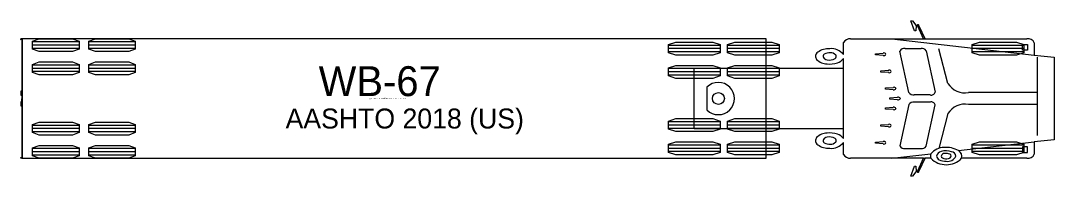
# Model space of a CAD drawing. Extents: x -69 to 14108008, y -6 to 8640172.
# Drawn here: x -69.5 to 4, y -5.5 to 5.5 of the extents above; entities that cross this region are included whole.
import ezdxf

# ---------------------------------------------------------------- set-up
doc = ezdxf.new("R2010")
doc.units = 0
doc.layers.add('AutoTurn4', color=7, linetype='Continuous')

msp = doc.modelspace()

# ---------------------------------------------------------------- linework, layer by layer
at = {"layer": 'AutoTurn4'}
for p, q in [((-5.834, 5.187), (-5.851, 5.209)), ((-5.835, 5.159), (-5.834, 5.187)), ((-69.359, -4.25), (-69.359, 4.25)), ((-65.35, 4.021), (-68.65, 4.021)), ((-65.35, 3.792), (-68.65, 3.792)), ((-61.35, 4.021), (-64.65, 4.021)), ((-61.35, 3.792), (-64.65, 3.792)), ((-19.767, 3.771), (-23.433, 3.771)), ((-15.567, 3.771), (-19.233, 3.771)), ((-11, 3.134), (-11, 3.979)), ((-7.561, 4.25), (2.573, 3.09)), ((-5.311, 4.25), (-5.211, 4.25)), ((1.833, 3.771), (-1.833, 3.771)), ((1.738, 3.841), (2.094, 3.841)), ((1.738, 3.428), (1.738, 3.841)), ((2.094, 3.841), (2.094, 3.428)), ((-65.35, 3.563), (-68.65, 3.563)), ((-61.35, 3.563), (-64.65, 3.563)), ((-19.767, 3.542), (-23.433, 3.542)), ((-19.767, 3.312), (-23.433, 3.312)), ((-15.567, 3.542), (-19.233, 3.542)), ((-15.567, 3.312), (-19.233, 3.312)), ((-8.727, 3.186), (-8.177, 3.225)), ((-8.727, 3.096), (-8.727, 3.186)), ((-8.177, 3.057), (-8.727, 3.096)), ((-6.336, 0.424), (-6.98, 3.36)), ((-6.61, 3.558), (-5.479, 3.558)), ((-5.109, 3.393), (-4.464, 0.457)), ((-3.572, 1.07), (-4.205, 3.537)), ((1.833, 3.542), (-1.833, 3.542)), ((1.833, 3.312), (-1.833, 3.312)), ((2.094, 3.428), (1.738, 3.428)), ((-65.35, 2.371), (-68.65, 2.371)), ((-61.35, 2.371), (-64.65, 2.371)), ((2.799, -2.637), (2.799, 2.926)), ((-65.35, 2.142), (-68.65, 2.142)), ((-65.35, 1.913), (-68.65, 1.913)), ((-61.35, 2.142), (-64.65, 2.142)), ((-61.35, 1.913), (-64.65, 1.913)), ((-19.767, 2.121), (-23.433, 2.121)), ((-19.767, 1.892), (-23.433, 1.892)), ((-19.767, 1.662), (-23.433, 1.662)), ((-15.567, 2.121), (-19.233, 2.121)), ((-15.567, 1.892), (-19.233, 1.892)), ((-15.567, 1.662), (-19.233, 1.662)), ((-11, -2.165), (-11, 2.165)), ((-8.341, 1.969), (-7.766, 2.009)), ((-8.341, 1.879), (-8.341, 1.969)), ((-7.766, 1.841), (-8.341, 1.879)), ((-20.698, 0.803), (-20.698, -0.813)), ((-8.007, 0.751), (-7.457, 0.791)), ((-8.007, 0.661), (-8.007, 0.751)), ((-69.429, 0.259), (-69.43, -0.262)), ((-69.429, 0.266), (-69.429, 0.531)), ((-69.429, 0), (-69.359, 0)), ((-7.457, 0.622), (-8.007, 0.661)), ((-7.698, 0.045), (-7.149, 0.084)), ((-7.698, -0.045), (-7.698, 0.045)), ((-4.835, 0.259), (-5.965, 0.259)), ((2.799, 0.417), (-2.093, 0.417)), ((-69.429, -0.531), (-69.429, -0.266)), ((-8.007, -0.661), (-7.457, -0.622)), ((-8.007, -0.751), (-8.007, -0.661)), ((-7.149, -0.084), (-7.698, -0.045)), ((-6.336, -0.424), (-6.98, -3.36)), ((-4.835, -0.259), (-5.965, -0.259)), ((-5.109, -3.393), (-4.464, -0.457)), ((2.799, -0.417), (-2.093, -0.417)), ((-7.457, -0.791), (-8.007, -0.751)), ((-3.572, -1.07), (-4.208, -3.55)), ((-65.35, -1.912), (-68.65, -1.912)), ((-65.35, -2.142), (-68.65, -2.142)), ((-61.35, -1.912), (-64.65, -1.912)), ((-61.35, -2.142), (-64.65, -2.142)), ((-19.767, -1.662), (-23.433, -1.662)), ((-19.767, -1.892), (-23.433, -1.892)), ((-19.767, -2.121), (-23.433, -2.121)), ((-15.567, -1.662), (-19.233, -1.662)), ((-15.567, -1.892), (-19.233, -1.892)), ((-15.567, -2.121), (-19.233, -2.121)), ((-8.341, -1.879), (-7.791, -1.84)), ((-8.341, -1.969), (-8.341, -1.879)), ((-7.791, -2.008), (-8.341, -1.969)), ((-65.35, -2.371), (-68.65, -2.371)), ((-61.35, -2.371), (-64.65, -2.371)), ((-65.35, -3.562), (-68.65, -3.562)), ((-61.35, -3.562), (-64.65, -3.562)), ((-19.767, -3.312), (-23.433, -3.312)), ((-19.767, -3.542), (-23.433, -3.542)), ((-15.567, -3.312), (-19.233, -3.312)), ((-15.567, -3.542), (-19.233, -3.542)), ((-11, -3.979), (-11, -3.134)), ((-8.727, -3.096), (-8.177, -3.057)), ((-8.727, -3.186), (-8.727, -3.096)), ((-8.177, -3.225), (-8.727, -3.186)), ((-6.61, -3.558), (-5.479, -3.558)), ((-2.818, -3.707), (2.573, -3.09)), ((1.833, -3.312), (-1.833, -3.312)), ((1.833, -3.542), (-1.833, -3.542)), ((2.094, -3.428), (1.738, -3.428)), ((1.738, -3.428), (1.738, -3.841)), ((2.094, -3.841), (2.094, -3.428)), ((-65.35, -3.792), (-68.65, -3.792)), ((-65.35, -4.021), (-68.65, -4.021)), ((-61.35, -3.792), (-64.65, -3.792)), ((-61.35, -4.021), (-64.65, -4.021)), ((-19.767, -3.771), (-23.433, -3.771)), ((-15.567, -3.771), (-19.233, -3.771)), ((-7.561, -4.25), (-4.773, -3.931)), ((-5.311, -4.25), (-5.211, -4.25)), ((2.053, -4.25), (-2.591, -4.25)), ((1.833, -3.771), (-1.833, -3.771)), ((1.738, -3.841), (2.094, -3.841)), ((-5.834, -5.187), (-5.851, -5.209)), ((-5.835, -5.159), (-5.834, -5.187))]:
    msp.add_line(p, q, dxfattribs=at)
for points in [[(-10.487, 4.25), (-5.311, 4.25), (-5.716, 5.146), (-5.717, 5.146), (-5.753, 5.158), (-5.754, 5.158), (-5.755, 5.158), (-5.835, 5.159), (-5.835, 5.158), (-5.851, 4.81), (-5.954, 4.81), (-6.211, 5.529), (-6.211, 5.531), (-6.092, 5.531), (-6.09, 5.529), (-5.852, 5.211), (-5.85, 5.209), (-5.763, 5.209)], [(-5.63, 5.164), (-5.215, 4.259), (-5.203, 4.25), (2.053, 4.25)], [(-69.43, 4.203), (-69.429, 4.203), (-69.429, 0.567), (-69.43, 0.531), (-69.499, 0.531), (-69.5, 0.53), (-69.5, 0.263)], [(-69.429, -4.228), (-69.429, -4.249), (-69.359, -4.249), (-63.692, -4.25), (-16.5, -4.25), (-16.5, 0), (-16.5, 4.25), (-63.692, 4.25), (-69.359, 4.249), (-69.429, 4.249), (-69.429, 4.228)], [(2.573, 3.955), (2.573, 3.098), (2.575, 3.089), (4, 2.926), (4, 2.863), (4, 0), (4, -2.863), (4, -2.926), (2.575, -3.089), (2.573, -3.098), (2.573, -3.955)], [(-11, -2.852), (-11, -2.166), (-11.238, -2.165), (-21.6, -2.165), (-21.6, 0), (-21.6, 2.165), (-11.238, 2.165), (-11, 2.166), (-11, 2.852)], [(-69.5, -0.263), (-69.5, -0.53), (-69.499, -0.531), (-69.43, -0.531), (-69.429, -0.567), (-69.429, -4.203), (-69.43, -4.203)], [(-5.763, -5.209), (-5.85, -5.209), (-5.852, -5.211), (-6.09, -5.529), (-6.092, -5.531), (-6.211, -5.531), (-6.211, -5.529), (-5.954, -4.81), (-5.851, -4.81), (-5.835, -5.158), (-5.835, -5.159), (-5.755, -5.158), (-5.754, -5.158), (-5.753, -5.158), (-5.717, -5.146), (-5.716, -5.146), (-5.311, -4.25), (-10.487, -4.25)], [(-4.777, -4.25), (-5.203, -4.25), (-5.215, -4.259), (-5.63, -5.164)]]:
    msp.add_lwpolyline(points, dxfattribs=at)
for points in [[(-65.35, 4.078), (-65.35, 3.506), (-65.812, 3.333), (-68.188, 3.333), (-68.65, 3.506), (-68.65, 4.078), (-68.188, 4.25), (-65.812, 4.25)], [(-61.35, 4.078), (-61.35, 3.506), (-61.812, 3.333), (-64.188, 3.333), (-64.65, 3.506), (-64.65, 4.078), (-64.188, 4.25), (-61.812, 4.25)], [(-19.767, 3.828), (-19.767, 3.256), (-20.28, 3.083), (-22.92, 3.083), (-23.433, 3.256), (-23.433, 3.828), (-22.92, 4), (-20.28, 4)], [(-15.567, 3.828), (-15.567, 3.256), (-16.08, 3.083), (-18.72, 3.083), (-19.233, 3.256), (-19.233, 3.828), (-18.72, 4), (-16.08, 4)], [(1.833, 3.828), (1.833, 3.256), (1.32, 3.083), (-1.32, 3.083), (-1.833, 3.256), (-1.833, 3.828), (-1.32, 4), (1.32, 4)], [(-65.35, 2.428), (-65.35, 1.856), (-65.812, 1.683), (-68.188, 1.683), (-68.65, 1.856), (-68.65, 2.428), (-68.188, 2.6), (-65.812, 2.6)], [(-61.35, 2.428), (-61.35, 1.856), (-61.812, 1.683), (-64.188, 1.683), (-64.65, 1.856), (-64.65, 2.428), (-64.188, 2.6), (-61.812, 2.6)], [(-19.767, 2.178), (-19.767, 1.606), (-20.28, 1.433), (-22.92, 1.433), (-23.433, 1.606), (-23.433, 2.178), (-22.92, 2.35), (-20.28, 2.35)], [(-15.567, 2.178), (-15.567, 1.606), (-16.08, 1.433), (-18.72, 1.433), (-19.233, 1.606), (-19.233, 2.178), (-18.72, 2.35), (-16.08, 2.35)], [(-19.767, -1.606), (-19.767, -2.178), (-20.28, -2.35), (-22.92, -2.35), (-23.433, -2.178), (-23.433, -1.606), (-22.92, -1.433), (-20.28, -1.433)], [(-15.567, -1.606), (-15.567, -2.178), (-16.08, -2.35), (-18.72, -2.35), (-19.233, -2.178), (-19.233, -1.606), (-18.72, -1.433), (-16.08, -1.433)], [(-65.35, -1.856), (-65.35, -2.428), (-65.812, -2.6), (-68.188, -2.6), (-68.65, -2.428), (-68.65, -1.856), (-68.188, -1.683), (-65.812, -1.683)], [(-61.35, -1.856), (-61.35, -2.428), (-61.812, -2.6), (-64.188, -2.6), (-64.65, -2.428), (-64.65, -1.856), (-64.188, -1.683), (-61.812, -1.683)], [(-65.35, -3.506), (-65.35, -4.078), (-65.812, -4.25), (-68.188, -4.25), (-68.65, -4.078), (-68.65, -3.506), (-68.188, -3.333), (-65.812, -3.333)], [(-61.35, -3.506), (-61.35, -4.078), (-61.812, -4.25), (-64.188, -4.25), (-64.65, -4.078), (-64.65, -3.506), (-64.188, -3.333), (-61.812, -3.333)], [(-19.767, -3.256), (-19.767, -3.828), (-20.28, -4), (-22.92, -4), (-23.433, -3.828), (-23.433, -3.256), (-22.92, -3.083), (-20.28, -3.083)], [(-15.567, -3.256), (-15.567, -3.828), (-16.08, -4), (-18.72, -4), (-19.233, -3.828), (-19.233, -3.256), (-18.72, -3.083), (-16.08, -3.083)], [(1.833, -3.256), (1.833, -3.828), (1.32, -4), (-1.32, -4), (-1.833, -3.828), (-1.833, -3.256), (-1.32, -3.083), (1.32, -3.083)]]:
    msp.add_lwpolyline(points, close=True, dxfattribs=at)
for centre, radius in [((-69.464, 4.216), 0.0266), ((-19.888, 0), 0.424), ((-69.464, -4.216), 0.0266)]:
    msp.add_circle(centre, radius, dxfattribs=at)
for centre, radius, start, end in [((-5.698, 5.123), 0.108, 80.84117, 127.02367), ((-5.68, 5.177), 0.0522, 346.26279, 91.1174), ((-69.464, 4.216), 0.0363, 19.07745, 340.23879), ((-10.487, 3.631), 0.619, 89.99798, 145.83969), ((2.124, 3.77), 0.486, 22.46296, 98.41407), ((-12.636, 2.998), 0.346, 123.3927, 220.40575), ((-12.014, 2.126), 1.416, 87.92815, 124.99601), ((-12.269, 2.993), 0.172, 120.3016, 207.4522), ((-11.992, 2.585), 0.664, 84.90383, 123.12554), ((-11.875, 2.409), 1.136, 39.62994, 94.42123), ((-11.914, 2.725), 0.522, 45.00537, 92.16949), ((-11.676, 2.99), 0.169, 298.43433, 38.55304), ((-8.122, 3.079), 0.157, 23.54598, 110.65564), ((-8.136, 3.237), 0.184, 256.95318, 328.8452), ((-6.674, 3.233), 0.332, 78.9214, 157.3434), ((-5.428, 3.175), 0.387, 34.33285, 97.56481), ((-12.107, 3.587), 1.136, 225.76396, 267.28471), ((-12.122, 3.118), 0.362, 214.29656, 263.33754), ((-11.977, 3.466), 0.732, 255.17382, 301.40826), ((-11.974, 4.173), 1.73, 263.82664, 288.62515), ((-11.62, 3.234), 0.729, 285.80849, 328.32248), ((-7.736, 1.861), 0.157, 23.54598, 110.65564), ((-7.75, 2.019), 0.184, 256.95318, 328.8452), ((-19.89, -0.005), 1.143, 225, 135), ((-7.402, 0.644), 0.157, 23.54598, 110.65564), ((-2.315, 1.917), 1.517, 213.99254, 278.41996), ((-69.465, 0.264), 0.0353, 3.33618, 181.68583), ((-69.465, 0.263), 0.0352, 180.02527, 359.02568), ((-7.416, 0.802), 0.184, 256.95318, 328.8452), ((-7.093, -0.063), 0.157, 23.54598, 110.65564), ((-6.016, 0.643), 0.387, 214.3353, 277.56236), ((-4.748, 0.542), 0.296, 252.98357, 343.28124), ((-69.465, -0.263), 0.0352, 0.97432, 179.97473), ((-69.465, -0.263), 0.0354, 184.29154, 356.477), ((-7.416, -0.802), 0.184, 31.1548, 103.04682), ((-7.402, -0.644), 0.157, 249.34436, 336.45402), ((-7.093, 0.063), 0.157, 249.34436, 336.45402), ((-6.016, -0.643), 0.387, 82.43764, 145.6647), ((-4.748, -0.542), 0.296, 16.71876, 107.01643), ((-2.315, -1.917), 1.517, 81.58004, 146.00746), ((-7.75, -2.019), 0.184, 31.1548, 103.04682), ((-7.736, -1.861), 0.157, 249.34436, 336.45402), ((-12.636, -2.998), 0.346, 139.59425, 236.6073), ((-12.107, -3.587), 1.136, 92.71529, 134.23604), ((-12.269, -2.993), 0.172, 152.5478, 239.6984), ((-12.122, -3.118), 0.362, 96.66246, 145.70344), ((-11.977, -3.466), 0.732, 58.59174, 104.82618), ((-11.974, -4.173), 1.73, 71.37485, 96.17336), ((-11.676, -2.99), 0.169, 321.44696, 61.56567), ((-11.62, -3.234), 0.729, 31.67752, 74.19151), ((-12.014, -2.126), 1.416, 235.00399, 272.07185), ((-11.992, -2.585), 0.664, 236.87446, 275.09617), ((-11.875, -2.409), 1.136, 265.57877, 320.37006), ((-11.914, -2.725), 0.522, 267.83051, 314.99463), ((-8.136, -3.237), 0.184, 31.1548, 103.04682), ((-8.122, -3.079), 0.157, 249.34436, 336.45402), ((-6.674, -3.233), 0.332, 202.6566, 281.0786), ((-5.428, -3.175), 0.387, 262.43519, 325.66715), ((-3.871, -4.622), 1.136, 88.70454, 142.50711), ((-3.672, -5.181), 1.704, 59.92068, 95.82875), ((-71.451, -4.228), 2.022, 0, 0.68376), ((-10.487, -3.631), 0.619, 214.16031, 270.00202), ((-4.465, -4.092), 0.347, 152.32721, 207.13779), ((-3.683, -3.178), 1.53, 224.49274, 315.50178), ((-3.949, -4.201), 0.44, 101.79424, 165.60709), ((-4.061, -4.06), 0.317, 185.85019, 247.4426), ((-3.712, -3.436), 1.03, 242.82365, 271.21016), ((-3.793, -4.169), 0.263, 88.93491, 162.83683), ((-3.875, -4.069), 0.17, 187.66906, 241.7334), ((-3.691, -4.908), 1.189, 71.1312, 107.02052), ((-3.686, -3.695), 0.589, 242.75553, 285.73824), ((-3.691, -4.474), 0.575, 63.07512, 99.64545), ((-3.587, -3.84), 0.634, 260.58386, 336.58558), ((-3.554, -4.041), 0.223, 277.2349, 346.83739), ((-3.494, -4.106), 0.158, 4.97122, 66.48397), ((-3.367, -4.143), 0.366, 8.05234, 80.53332), ((-3.001, -4.091), 0.425, 338.06293, 64.5993), ((2.124, -3.77), 0.486, 261.58593, 337.53704), ((-5.698, -5.123), 0.108, 232.97633, 279.15883), ((-5.68, -5.177), 0.0522, 268.8826, 13.73721)]:
    msp.add_arc(centre, radius, start, end, dxfattribs=at)
for centre, major_axis, start_param, end_param in [((-5.696, 5.187), (0.0782, 0), 2.615166, 3.884468), ((-5.696, 5.187), (-0.0782, 0), 1.301202, 2.571945), ((-5.696, -5.187), (0.0782, 0), 0.569648, 1.840391), ((-5.696, -5.187), (0.0782, 0), 2.398717, 3.668019)]:
    msp.add_ellipse(centre, major_axis=major_axis, ratio=0.544872, start_param=start_param, end_param=end_param, dxfattribs=at)

# ---------------------------------------------------------------- texts
for s, height, p in [('WB-67', 2.125, (-48.312, 0.17)), ('(c) 2023 Transoft Solutions, Inc. All rights reserved.', 0.085, (-44.74, -0.042)), ('AASHTO 2018 (US)', 1.41667, (-50.665, -2.132))]:
    msp.add_text(s, height=height, dxfattribs=at).set_placement(p)

doc.saveas('drawing.dxf')
